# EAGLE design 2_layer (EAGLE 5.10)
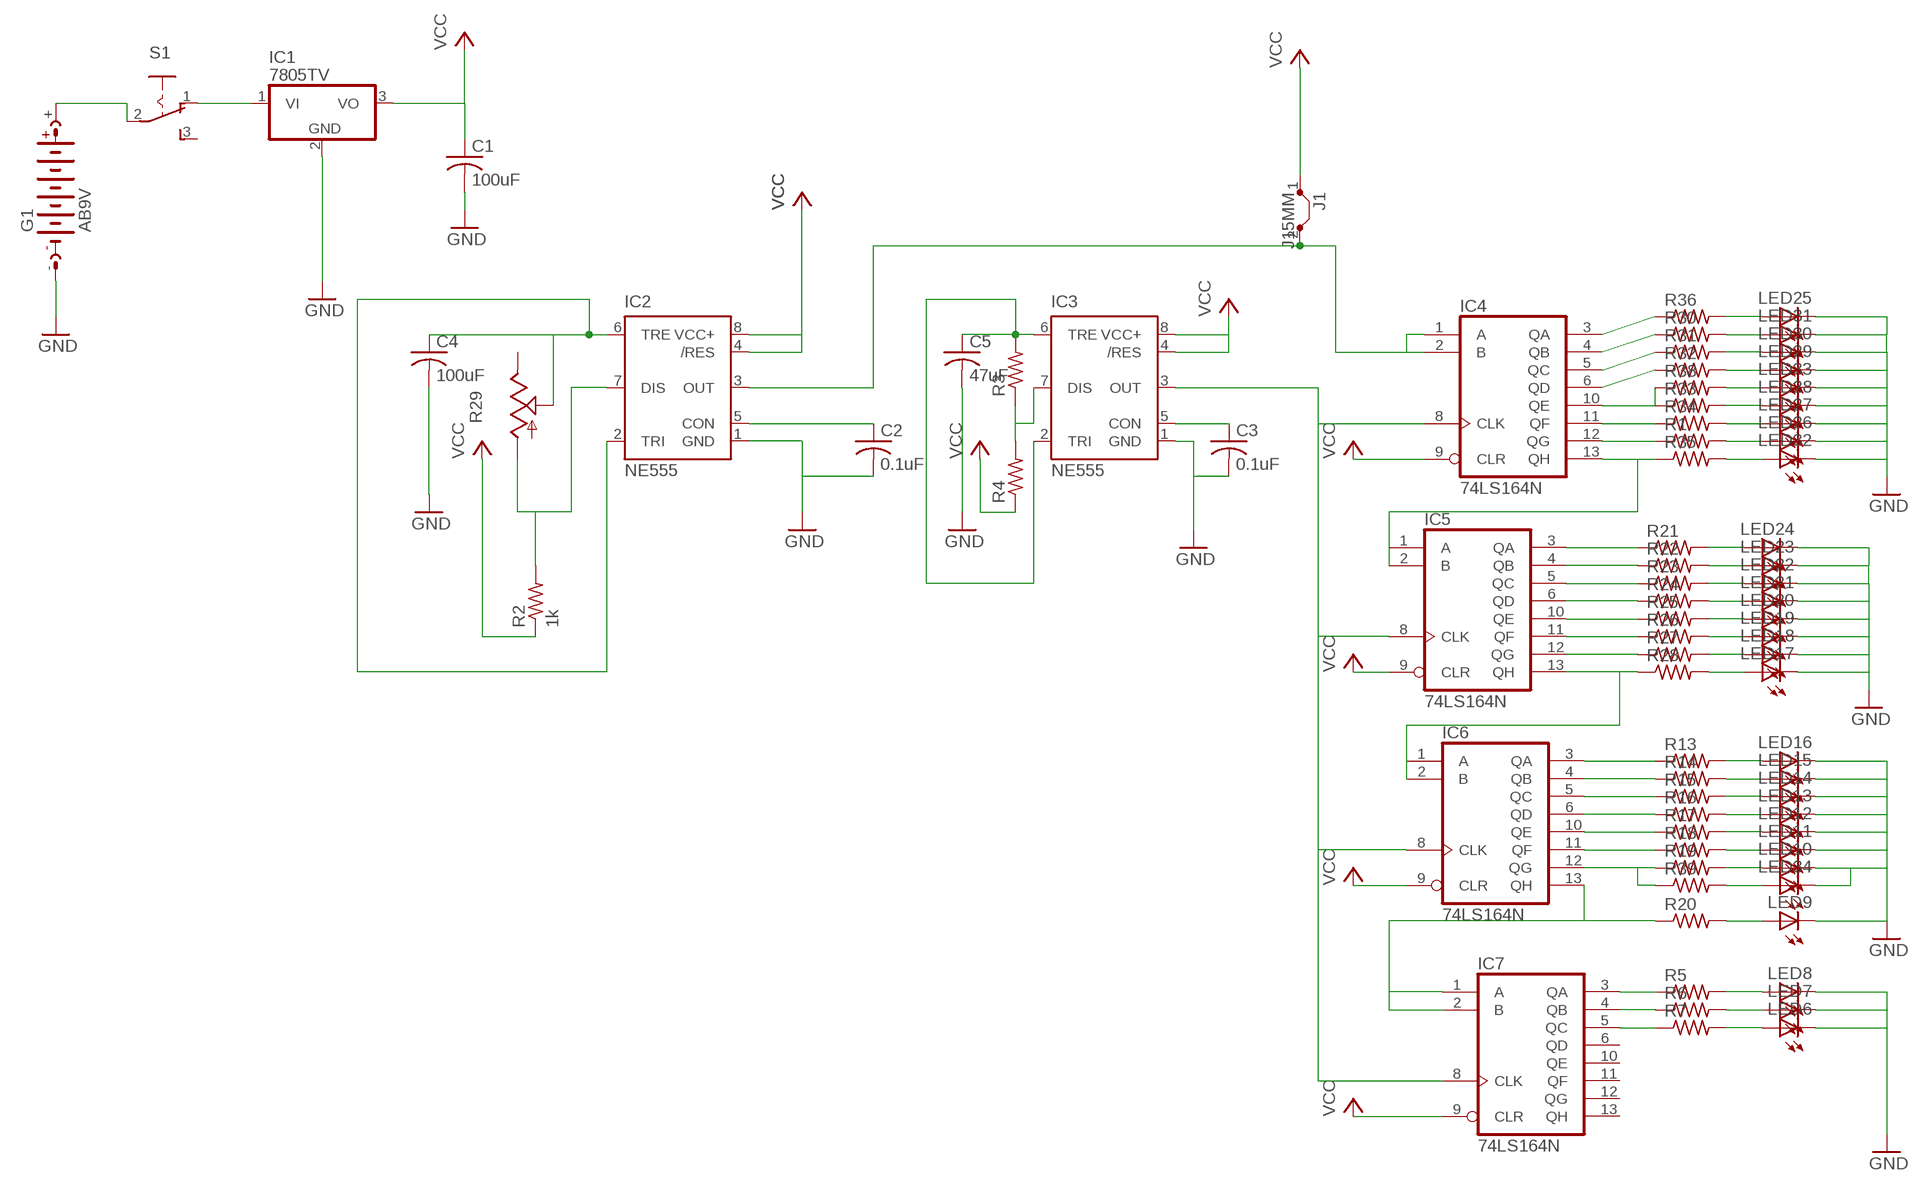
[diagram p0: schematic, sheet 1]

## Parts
C1  100uF  C-US025-025X050  [C025-025X050]
C2  0.1uF  C-US025-025X050  [C025-025X050]
C3  0.1uF  C-US025-025X050  [C025-025X050]
C4  100uF  C-US025-025X050  [C025-025X050]
C5  47uF  C-US025-025X050  [C025-025X050]
G1  AB9V  [AB9V]
IC1  7805TV  [TO220V]
IC2  NE555  [DIL-08]
IC3  NE555  [DIL-08]
IC4  74LS164N  [DIL14]
IC5  74LS164N  [DIL14]
IC6  74LS164N  [DIL14]
IC7  74LS164N  [DIL14]
J1  J15MM  [15]
LED6  LED5MM  [LED5MM]
LED7  LED5MM  [LED5MM]
LED8  LED5MM  [LED5MM]
LED9  LED5MM  [LED5MM]
LED10  LED5MM  [LED5MM]
LED11  LED5MM  [LED5MM]
LED12  LED5MM  [LED5MM]
LED13  LED5MM  [LED5MM]
LED14  LED5MM  [LED5MM]
LED15  LED5MM  [LED5MM]
LED16  LED5MM  [LED5MM]
LED17  LED5MM  [LED5MM]
LED18  LED5MM  [LED5MM]
LED19  LED5MM  [LED5MM]
LED20  LED5MM  [LED5MM]
LED21  LED5MM  [LED5MM]
LED22  LED5MM  [LED5MM]
LED23  LED5MM  [LED5MM]
LED24  LED5MM  [LED5MM]
LED25  LED5MM  [LED5MM]
LED26  LED5MM  [LED5MM]
LED27  LED5MM  [LED5MM]
LED28  LED5MM  [LED5MM]
LED29  LED5MM  [LED5MM]
LED30  LED5MM  [LED5MM]
LED31  LED5MM  [LED5MM]
LED32  LED5MM  [LED5MM]
LED33  LED5MM  [LED5MM]
LED34  LED5MM  [LED5MM]
R1  R-US_0207/12  [0207/12]
R2  1k  R-US_0207/7  [0207/7]
R3  R-US_0207/7  [0207/7]
R4  R-US_0207/7  [0207/7]
R5  R-US_0207/12  [0207/12]
R6  R-US_0207/12  [0207/12]
R7  R-US_0207/12  [0207/12]
R13  R-US_0207/12  [0207/12]
R14  R-US_0207/12  [0207/12]
R15  R-US_0207/12  [0207/12]
R16  R-US_0207/12  [0207/12]
R17  R-US_0207/12  [0207/12]
R18  R-US_0207/12  [0207/12]
R19  R-US_0207/12  [0207/12]
R20  R-US_0207/12  [0207/12]
R21  R-US_0207/12  [0207/12]
R22  R-US_0207/12  [0207/12]
R23  R-US_0207/12  [0207/12]
R24  R-US_0207/12  [0207/12]
R25  R-US_0207/12  [0207/12]
R26  R-US_0207/12  [0207/12]
R27  R-US_0207/12  [0207/12]
R28  R-US_0207/12  [0207/12]
R29  TRIM_US-S75P  [S75P]
R30  R-US_0207/12  [0207/12]
R31  R-US_0207/12  [0207/12]
R32  R-US_0207/12  [0207/12]
R33  R-US_0207/12  [0207/12]
R34  R-US_0207/12  [0207/12]
R35  R-US_0207/12  [0207/12]
R36  R-US_0207/12  [0207/12]
R38  R-US_0207/12  [0207/12]
R39  R-US_0207/12  [0207/12]
S1  255SB  [255SB]

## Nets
GND: C1.2 C2.2 C3.2 C4.2 C5.2 G1.- IC1.2(GND) IC2.1(GND) IC3.1(GND) LED6.K(C) LED7.K(C) LED8.K(C) LED9.K(C) LED10.K(C) LED11.K(C) LED12.K(C) LED13.K(C) LED14.K(C) LED15.K(C) LED16.K(C) LED17.K(C) LED18.K(C) LED19.K(C) LED20.K(C) LED21.K(C) LED22.K(C) LED23.K(C) LED24.K(C) LED25.K(C) LED26.K(C) LED27.K(C) LED28.K(C) LED29.K(C) LED30.K(C) LED31.K(C) LED32.K(C) LED33.K(C) LED34.K(C)
N$1: G1.+ S1.2(P)
N$2: C3.1 IC3.5(CON)
N$3: C2.1 IC2.5(CON)
N$4: C4.1 IC2.2(TRI) IC2.6(TRE) R29.S
N$5: C5.1 IC3.2(TRI) IC3.6(TRE) R3.2
N$6: IC2.7(DIS) R2.2 R29.A
N$7: IC2.3(OUT) IC4.1(A) IC4.2(B) J1.2
N$8: IC3.7(DIS) R3.1 R4.2
N$9: IC6.13(QH) IC7.1(A) IC7.2(B) R20.1
N$10: IC3.3(OUT) IC4.8(CLK) IC5.8(CLK) IC6.8(CLK) IC7.8(CLK)
N$11: IC4.12(QG) R1.1
N$12: IC5.13(QH) IC6.1(A) IC6.2(B) R28.1
N$13: IC7.3(QA) R5.1
N$14: IC7.4(QB) R6.1
N$15: IC7.5(QC) R7.1
N$26: LED6.A R7.2
N$27: LED7.A R6.2
N$28: LED8.A R5.2
N$29: IC6.3(QA) R13.1
N$30: IC6.4(QB) R14.1
N$31: IC6.5(QC) R15.1
N$32: IC6.6(QD) R16.1
N$33: IC6.10(QE) R17.1
N$34: IC6.12(QG) R19.1 R39.1
N$35: IC6.11(QF) R18.1
N$36: LED26.A R1.2
N$37: LED9.A R20.2
N$38: LED10.A R19.2
N$39: LED11.A R18.2
N$40: LED12.A R17.2
N$41: LED13.A R16.2
N$42: LED14.A R15.2
N$43: LED15.A R14.2
N$44: LED16.A R13.2
N$45: IC5.3(QA) R21.1
N$46: IC5.4(QB) R22.1
N$47: IC5.5(QC) R23.1
N$48: IC5.6(QD) R24.1
N$49: IC5.10(QE) R25.1
N$50: IC5.12(QG) R27.1
N$51: IC5.11(QF) R26.1
N$52: LED32.A R35.2
N$53: LED17.A R28.2
N$54: LED18.A R27.2
N$55: LED19.A R26.2
N$56: LED20.A R25.2
N$57: LED21.A R24.2
N$58: LED22.A R23.2
N$59: LED23.A R22.2
N$60: LED24.A R21.2
N$61: LED25.A R36.2
N$62: IC4.4(QB) R30.1
N$63: IC4.5(QC) R31.1
N$64: IC4.6(QD) R32.1
N$65: IC4.10(QE) R33.1 R38.1
N$66: IC4.3(QA) R36.1
N$67: IC4.11(QF) R34.1
N$68: IC4.13(QH) IC5.1(A) IC5.2(B) R35.1
N$69: LED34.A R39.2
N$70: LED33.A R38.2
N$71: LED27.A R34.2
N$72: LED28.A R33.2
N$73: LED29.A R32.2
N$74: LED30.A R31.2
N$75: LED31.A R30.2
N$77: IC1.1(VI) S1.1(O)
VCC: C1.1 IC1.3(VO) IC2.4(/RES) IC2.8(VCC+) IC3.4(/RES) IC3.8(VCC+) IC4.9(CLR) IC5.9(CLR) IC6.9(CLR) IC7.9(CLR) J1.1 R2.1 R4.1
Unconnected: IC7.6(QD) IC7.10(QE) IC7.11(QF) IC7.12(QG) IC7.13(QH) R29.E S1.3(S)

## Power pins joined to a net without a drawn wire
GND: IC4.7(GND) IC5.7(GND) IC6.7(GND) IC7.7(GND)
VCC: IC4.14(VCC) IC5.14(VCC) IC6.14(VCC) IC7.14(VCC)

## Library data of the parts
C1-C5 = resistor:C-US: CAPACITOR, American symbol
G1 = battery:AB9V: 9-V BATTERY CLIP
IC1 = linear:78*: Positive VOLTAGE REGULATOR Source: http://cache.national.com/ds/LM/LM78L05.pdf http://www.fairchildsemi.com/ds/LM/LM7805.pdf
IC2 IC3 = st-microelectronics:NE555: General purpose bipolar Timer
IC4-IC7 = 74xx-us:74*164: 8-bit parallel out SHIFT REGISTER
J1 = jumper:J: Bridge
LED6-LED34 = led:LED: LED
R1-R7 R13-R28 R30-R36 R38 R39 = resistor:R-US_: RESISTOR, American symbol
R29 = pot:TRIM_US-: POTENTIOMETER
S1 = switch:255SB: SLIDING SWITCH Distributor Buerklin, 11G810

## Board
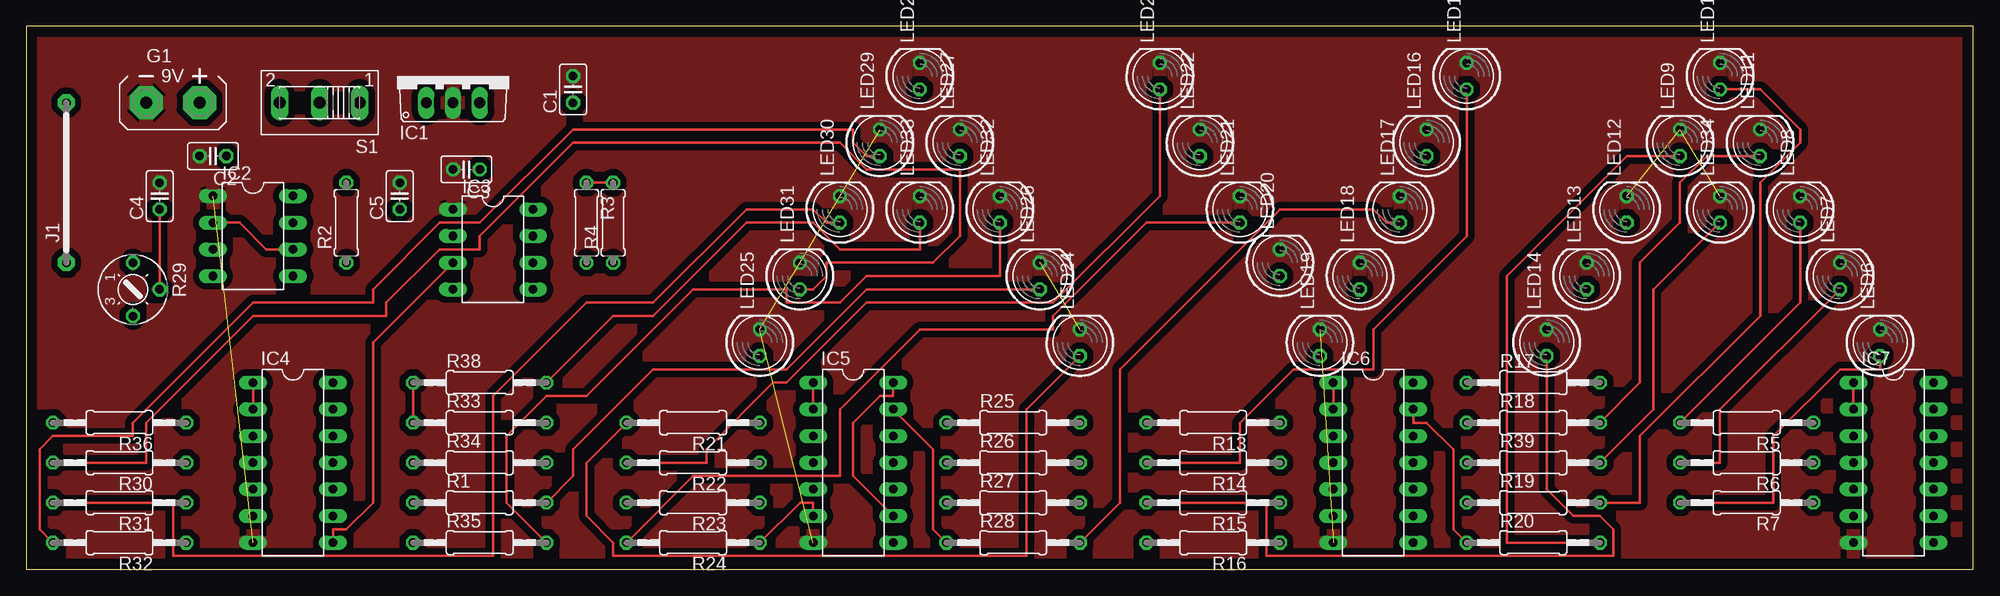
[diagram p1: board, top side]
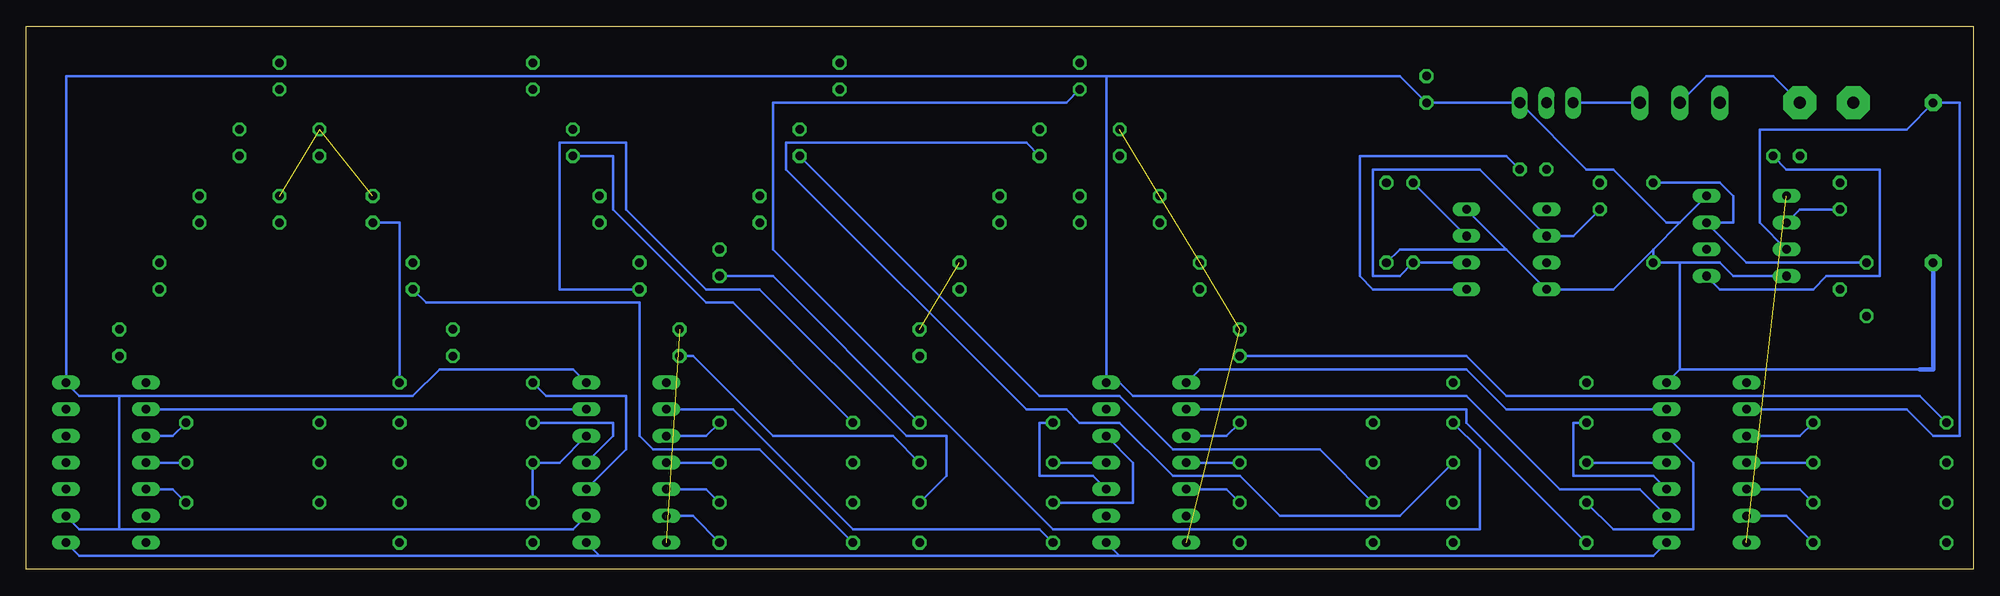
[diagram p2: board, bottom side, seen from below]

Size 185.4 x 51.74 mm. Coordinates in mm from the lower left corner, seen from the top.
Outline: 0,0 185.4,0 185.4,51.74 0,51.74 0,0
Copper layers (1*16): Top 0.035mm / dielectric 1.5mm / Bottom 0.035mm
Design rules "default": minimum track width 10mil, minimum drill 24mil, track to track 8mil, track to pad 8mil, pad to pad 8mil, via to via 8mil, smd to smd 8mil, copper to edge 40mil, drill to drill 8mil, minimum pad ring 10mil, minimum via ring 8mil, stop-mask expansion 4mil, vias tented up to drill 0mil, thermal gap 10mil

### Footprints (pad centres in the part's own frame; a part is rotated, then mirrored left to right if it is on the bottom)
C025-025X050 = drill 0.813 octagon: 1 -1.27,0; 2 1.27,0
AB9V = drill 1.118 pad 3.15 octagon: + 0,2.54; - 0,-2.54
TO220V = drill 1.016 long: 1 -2.54,-2.54; 2 0,-2.54; 3 2.54,-2.54
DIL-08 = drill 0.813 long: 1 -3.81,-3.81; 2 -1.27,-3.81; 3 1.27,-3.81; 4 3.81,-3.81; 5 3.81,3.81; 6 1.27,3.81; 7 -1.27,3.81; 8 -3.81,3.81
DIL14 = drill 0.813 long: 1 -7.62,-3.81; 2 -5.08,-3.81; 3 -2.54,-3.81; 4 0,-3.81; 5 2.54,-3.81; 6 5.08,-3.81; 7 7.62,-3.81; 8 7.62,3.81; 9 5.08,3.81; 10 2.54,3.81; 11 0,3.81; 12 -2.54,3.81; 13 -5.08,3.81; 14 -7.62,3.81
15 = drill 0.813 pad 1.6 octagon: 1 -7.62,0; 2 7.62,0
LED5MM = drill 0.813 octagon: A -1.27,0; K 1.27,0
0207/12 = drill 0.813 octagon: 1 -6.35,0; 2 6.35,0
0207/7 = drill 0.813 octagon: 1 -3.81,0; 2 3.81,0
S75P = drill 0.813 octagon: A -2.54,0; E 2.54,0; S 0,2.54
255SB = drill 1.118 long: 1 -3.81,0; 2 0,0; 3 3.81,0

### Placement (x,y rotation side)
C1  52.07,45.72 90 top
C2  17.78,39.37 180 top
C3  41.91,38.1 180 top
C4  12.7,35.56 90 top
C5  35.56,35.56 90 top
G1  13.97,44.45 270 top
IC1  40.64,46.99 0 top
IC2  21.59,31.75 270 top
IC3  44.45,30.48 270 top
IC4  25.4,10.16 270 top
IC5  78.74,10.16 270 top
IC6  128.27,10.16 270 top
IC7  177.8,10.16 270 top
J1  3.81,36.83 90 top
LED6  176.53,21.59 90 top
LED7  172.72,27.94 90 top
LED8  168.91,34.29 90 top
LED9  157.48,40.64 90 top
LED10  161.29,46.99 90 top
LED11  165.1,40.64 90 top
LED12  152.4,34.29 90 top
LED13  148.59,27.94 90 top
LED14  144.78,21.59 90 top
LED15  137.16,46.99 90 top
LED16  133.35,40.64 90 top
LED17  130.81,34.29 90 top
LED18  127,27.94 90 top
LED19  123.19,21.59 90 top
LED20  119.38,29.21 90 top
LED21  115.57,34.29 90 top
LED22  111.76,40.64 90 top
LED23  107.95,46.99 90 top
LED24  100.33,21.59 90 top
LED25  69.85,21.59 90 top
LED26  96.52,27.94 90 top
LED27  88.9,40.64 90 top
LED28  85.09,46.99 90 top
LED29  81.28,40.64 90 top
LED30  77.47,34.29 90 top
LED31  73.66,27.94 90 top
LED32  92.71,34.29 90 top
LED33  85.09,34.29 90 top
LED34  161.29,34.29 90 top
R1  43.18,6.35 0 top
R2  30.48,33.02 90 top
R3  53.34,33.02 270 top
R4  55.88,33.02 90 top
R5  163.83,13.97 180 top
R6  163.83,10.16 180 top
R7  163.83,6.35 180 top
R13  113.03,13.97 180 top
R14  113.03,10.16 180 top
R15  113.03,6.35 180 top
R16  113.03,2.54 180 top
R17  143.51,17.78 0 top
R18  143.51,13.97 0 top
R19  143.51,6.35 0 top
R20  143.51,2.54 0 top
R21  63.5,13.97 180 top
R22  63.5,10.16 180 top
R23  63.5,6.35 180 top
R24  63.5,2.54 180 top
R25  93.98,13.97 0 top
R26  93.98,10.16 0 top
R27  93.98,6.35 0 top
R28  93.98,2.54 0 top
R29  10.16,26.67 270 top
R30  8.89,10.16 180 top
R31  8.89,6.35 180 top
R32  8.89,2.54 180 top
R33  43.18,13.97 0 top
R34  43.18,10.16 0 top
R35  43.18,2.54 0 top
R36  8.89,13.97 180 top
R38  43.18,17.78 0 top
R39  143.51,10.16 0 top
S1  27.94,44.45 180 top

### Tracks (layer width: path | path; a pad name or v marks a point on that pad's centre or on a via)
GND  (9 unrouted)
  pour Top (isolate 0.61): 0,52.07 185.42,50.8 185.42,0 0,0
N$1
  Bottom 0.254: S1.2 25.4,46.99 19.05,46.99 G1.+
N$2
  Bottom 0.254: IC3.5 57.15,26.67 58.42,27.94 58.42,39.37 44.45,39.37 C3.1
N$3
  Bottom 0.254: IC2.5 24.13,26.67 15.24,26.67 13.97,27.94 8.89,27.94 8.89,38.1 17.78,38.1 C2.1
N$4
  Top 0.254: R29.S C4.1 | IC2.6 22.86,30.48 20.32,33.02 IC2.2
  Bottom 0.254: IC2.2 16.51,34.29 C4.1
N$5
  Bottom 0.254: IC3.6 R3.2 54.61,27.94 57.15,27.94 57.15,38.1 46.99,38.1 IC3.2 38.1,31.75 C5.1
N$6
  Bottom 0.254: R29.A 21.59,29.21 IC2.7 22.86,33.02 22.86,35.56 24.13,36.83 R2.2
N$7
  Top 0.254: IC4.2 IC4.1
  Bottom 0.254: IC2.3 20.32,33.02 20.32,41.91 6.35,41.91 J1.2 1.27,44.45 1.27,12.7 3.81,12.7 6.35,15.24 IC4.2
N$8
  Top 0.254: R3.1 R4.2
  Bottom 0.254: IC3.7 R3.1
N$9
  Top 0.254: IC7.2 IC7.1 | R20.1 135.89,3.81 135.89,11.43 133.35,13.97 132.08,13.97 IC6.13
  Bottom 0.254: IC6.13 IC7.2
N$10
  Top 0.254: IC3.3 33.02,21.59 33.02,6.35 30.48,3.81 29.21,3.81 IC4.8
  Bottom 0.254: IC4.8 30.48,1.27 81.28,1.27 | 81.28,1.27 IC5.8 | 130.81,1.27 IC6.8 | 81.28,1.27 130.81,1.27 | IC7.8 180.34,1.27 130.81,1.27
N$11
  Bottom 0.254: IC4.12 26.67,10.16 26.67,3.81 34.29,3.81 R1.1
N$12
  Top 0.254: IC6.2 IC6.1 | IC5.13 86.36,11.43 86.36,3.81 R28.1
  Bottom 0.254: IC6.2 118.11,15.24 106.68,3.81 88.9,3.81 R28.1
N$13
  Bottom 0.254: R5.1 171.45,12.7 IC7.3
N$14
  Bottom 0.254: R6.1 IC7.4
N$15
  Bottom 0.254: R7.1 171.45,7.62 IC7.5
N$26
  Top 0.254: R7.2 166.37,6.35 166.37,12.7 172.72,19.05 176.53,19.05 LED6.A
N$27
  Top 0.254: R6.2 161.29,10.16 161.29,15.24 LED7.A
N$28
  Top 0.254: R5.2 168.91,25.4 LED8.A
N$29
  Bottom 0.254: R13.1 120.65,12.7 IC6.3
N$30
  Bottom 0.254: R14.1 IC6.4
N$31
  Bottom 0.254: R15.1 120.65,7.62 IC6.5
N$32
  Bottom 0.254: R16.1 121.92,5.08 IC6.6
N$33
  Bottom 0.254: IC6.10 128.27,11.43 128.27,16.51 135.89,16.51 R17.1
N$34
  Bottom 0.254: R19.1 R39.1 134.62,10.16 IC6.12
N$35
  Bottom 0.254: IC6.11 129.54,12.7 129.54,13.97 R18.1
N$36
  Top 0.254: R1.2 52.07,8.89 52.07,11.43 59.69,19.05 72.39,19.05 80.01,26.67 LED26.A
N$37
  Top 0.254: R20.2 140.97,2.54 140.97,27.94 152.4,39.37 LED9.A
N$38
  Top 0.254: R19.2 153.67,6.35 153.67,12.7 165.1,24.13 165.1,36.83 168.91,40.64 168.91,41.91 165.1,45.72 LED10.A
N$39
  Top 0.254: R18.2 153.67,17.78 153.67,29.21 157.48,33.02 157.48,36.83 160.02,39.37 LED11.A
N$40
  Bottom 0.254: R17.2 149.86,33.02 LED12.A
N$41
  Bottom 0.254: R16.2 115.57,11.43 125.73,11.43 127,12.7 127,25.4 147.32,25.4 LED13.A
N$42
  Top 0.254: R15.2 118.11,6.35 118.11,1.27 151.13,1.27 151.13,3.81 149.86,5.08 147.32,5.08 144.78,7.62 LED14.A
N$43
  Top 0.254: R14.2 115.57,10.16 115.57,13.97 120.65,19.05 128.27,19.05 128.27,22.86 137.16,31.75 LED15.A
N$44
  Bottom 0.254: R13.2 118.11,25.4 120.65,25.4 129.54,34.29 129.54,39.37 LED16.A
N$45
  Bottom 0.254: R21.1 71.12,12.7 IC5.3
N$46
  Bottom 0.254: R22.1 IC5.4
N$47
  Bottom 0.254: R23.1 71.12,7.62 IC5.5
N$48
  Top 0.254: R24.1 73.66,6.35 74.93,6.35 IC5.6
N$49
  Bottom 0.254: IC5.10 83.82,8.89 88.9,8.89 88.9,13.97 R25.1
N$50
  Bottom 0.254: IC5.12 80.01,10.16 80.01,6.35 R27.1
N$51
  Bottom 0.254: IC5.11 R26.1
N$52
  Top 0.254: R35.2 45.72,6.35 45.72,12.7 49.53,16.51 53.34,16.51 63.5,26.67 72.39,26.67 72.39,25.4 77.47,25.4 80.01,27.94 92.71,27.94 LED32.A
N$53
  Top 0.254: R28.2 104.14,6.35 104.14,19.05 119.38,34.29 128.27,34.29 129.54,33.02 LED17.A
N$54
  Bottom 0.254: R27.2 97.79,8.89 97.79,12.7 101.6,12.7 115.57,26.67 120.65,26.67 128.27,34.29 128.27,40.64 134.62,40.64 134.62,26.67 LED18.A
N$55
  Bottom 0.254: R26.2 102.87,12.7 114.3,12.7 121.92,20.32 LED19.A
N$56
  Bottom 0.254: R25.2 114.3,27.94 LED20.A
N$57
  Top 0.254: R24.2 63.5,8.89 77.47,8.89 77.47,15.24 85.09,22.86 97.79,22.86 97.79,24.13 106.68,33.02 LED21.A
N$58
  Bottom 0.254: R23.2 62.23,11.43 76.2,11.43 81.28,16.51 88.9,16.51 LED22.A
N$59
  Top 0.254: R22.2 64.77,10.16 64.77,11.43 71.12,17.78 72.39,17.78 80.01,25.4 97.79,25.4 107.95,35.56 LED23.A
N$60
  Top 0.254: R21.2 53.34,10.16 53.34,5.08 55.88,2.54 55.88,1.27 95.25,1.27 95.25,15.24 LED24.A
N$61
  Bottom 0.254: R36.2 5.08,16.51 44.45,16.51 48.26,20.32 LED25.A
N$62
  Bottom 0.254: R30.1 IC4.4
N$63
  Bottom 0.254: R31.1 16.51,7.62 IC4.5
N$64
  Bottom 0.254: R32.1 17.78,5.08 IC4.6
N$65
  Top 0.254: R33.1 R38.1
  Bottom 0.254: IC4.10 30.48,8.89 38.1,8.89 38.1,13.97 R33.1
N$66
  Bottom 0.254: R36.1 16.51,12.7 IC4.3
N$67
  Bottom 0.254: IC4.11 R34.1
N$68
  Top 0.254: IC5.2 IC5.1
  Bottom 0.254: IC4.13 44.45,15.24 48.26,19.05 73.66,19.05 IC5.1 | R35.1 48.26,13.97 48.26,15.24 IC5.2
N$69
  Top 0.254: R39.2 154.94,15.24 154.94,26.67 LED34.A
N$70
  Top 0.254: R38.2 55.88,24.13 59.69,24.13 68.58,33.02 74.93,33.02 77.47,30.48 85.09,30.48 LED33.A
N$71
  Bottom 0.254: R34.2 54.61,5.08 66.04,5.08 69.85,8.89 76.2,8.89 81.28,13.97 85.09,13.97 86.36,15.24 90.17,15.24 113.03,38.1 113.03,40.64 90.17,40.64 LED27.A
N$72
  Bottom 0.254: R33.2 46.99,11.43 46.99,3.81 87.63,3.81 114.3,30.48 114.3,44.45 86.36,44.45 LED28.A
N$73
  Top 0.254: R32.2 1.27,3.81 1.27,11.43 2.54,12.7 10.16,12.7 10.16,13.97 21.59,25.4 33.02,25.4 33.02,26.67 39.37,33.02 43.18,33.02 52.07,41.91 78.74,41.91 78.74,40.64 80.01,39.37 LED29.A
N$74
  Top 0.254: R31.2 13.97,6.35 13.97,1.27 44.45,1.27 44.45,16.51 53.34,25.4 59.69,25.4 68.58,34.29 74.93,34.29 76.2,33.02 LED30.A
N$75
  Top 0.254: R30.2 11.43,10.16 11.43,13.97 21.59,24.13 34.29,24.13 34.29,25.4 39.37,30.48 43.18,30.48 43.18,31.75 52.07,40.64 77.47,40.64 80.01,38.1 88.9,38.1 88.9,31.75 86.36,29.21 76.2,29.21 76.2,27.94 74.93,26.67 LED31.A
N$77
  Bottom 0.254: S1.1 IC1.1
VCC
  Top 0.254: IC5.9 78.74,8.89 78.74,13.97 81.28,16.51 82.55,16.51 IC5.14
  Bottom 0.254: IC4.9 31.75,7.62 39.37,7.62 48.26,16.51 80.01,16.51 81.28,17.78 IC5.14 82.55,46.99 | IC6.9 133.35,3.81 176.53,3.81 | 176.53,3.81 180.34,3.81 IC7.9 | IC6.14 133.35,19.05 146.05,19.05 148.59,16.51 176.53,16.51 | 176.53,16.51 180.34,16.51 IC7.14 181.61,46.99 82.55,46.99 | 176.53,16.51 176.53,3.81 | 5.08,19.05 27.94,19.05 | 27.94,19.05 IC4.14 | IC2.4 22.86,27.94 24.13,29.21 27.94,29.21 | 27.94,29.21 R2.1 30.48,30.48 | 30.48,30.48 34.29,26.67 IC3.4 44.45,30.48 | 30.48,30.48 27.94,33.02 | 27.94,33.02 IC2.8 | 44.45,30.48 IC3.8 | R4.1 54.61,30.48 44.45,30.48 | 27.94,33.02 29.21,33.02 34.29,38.1 36.83,38.1 IC1.3 C1.1 54.61,46.99 82.55,46.99 | 27.94,19.05 27.94,29.21
  Bottom 0.406: 5.08,19.05 3.81,19.05 J1.1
